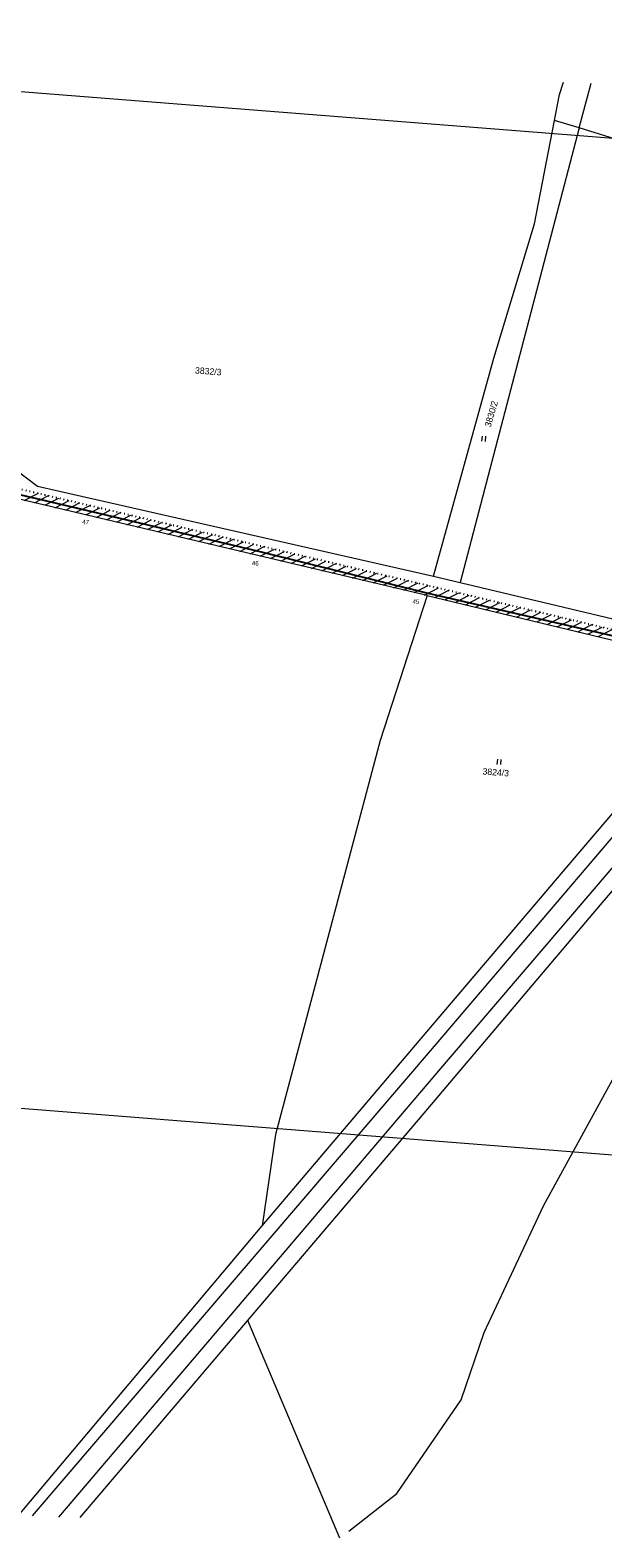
# Model space of a CAD drawing. Extents: x -686682 to -685519, y -959675 to -959188.
# Drawn here: x -686425.7 to -686257.7, y -959630.4 to -959188.4 of the extents above; entities that cross this region are included whole.
import ezdxf

# ---------------------------------------------------------------- set-up
doc = ezdxf.new("R2010")
doc.units = 0
doc.header["$LTSCALE"] = 0.76
doc.linetypes.add('DOTTED', pattern=[1.5, 0.3, -1.2])
for name, color, linetype, lineweight in [('1', 7, 'Continuous', 13), ('2', 7, 'Continuous', 25), ('3', 7, 'Continuous', 13)]:
    doc.layers.add(name, color=color, linetype=linetype, lineweight=lineweight)

msp = doc.modelspace()

# ---------------------------------------------------------------- linework, layer by layer
at = {"layer": '1'}
for p, q in [((-686270.4, -959207.3), (-686269.309, -959203.717)), ((-686264.72, -959217.11), (-686261.186, -959204.032)), ((-686264.72, -959217.11), (-686299.547, -959350.353)), ((-686264.72, -959217.11), (-686271.87, -959214.9)), ((-686159.97, -959249.46), (-686264.72, -959217.11)), ((-686293.16, -959307.411), (-686293.277, -959308.907)), ((-686292.163, -959307.49), (-686292.28, -959308.985)), ((-686288.662, -959402.161), (-686288.779, -959403.657)), ((-686287.665, -959402.24), (-686287.782, -959403.735)), ((-686307.203, -959486.217), (-686425.131, -959623.929)), ((-686417.348, -959624.293), (-686302.965, -959490.206)), ((-686362.008, -959566.628), (-686334.948, -959630.387))]:
    msp.add_line(p, q, dxfattribs=at)
for points in [[(-686681.662, -959484.53), (-685585.053, -959570.835), (-685561.751, -959274.75), (-686658.36, -959188.445)], [(-686407.67, -959329.7), (-686407.67, -959329.5), (-686407.47, -959329.5), (-686407.47, -959329.7)], [(-686357.95, -959341.59), (-686357.95, -959341.39), (-686357.75, -959341.39), (-686357.75, -959341.59)], [(-686309.41, -959353.59), (-686309.41, -959353.39), (-686309.21, -959353.39), (-686309.21, -959353.59)]]:
    msp.add_lwpolyline(points, close=True, dxfattribs=at)
for points in [[(-686307.4, -959348.5), (-686289.7, -959284.6), (-686277.74, -959245.2), (-686271.87, -959214.9), (-686270.4, -959207.3)], [(-686309.3, -959354.2), (-686524.18, -959303.43), (-686541.702, -959398.796)], [(-686458.24, -959312.86), (-686451.732, -959314.227), (-686446.754, -959312.429), (-686430.025, -959317.268), (-686423.527, -959322.107), (-686307.4, -959348.5), (-686224.763, -959368.147), (-686220.097, -959362.081), (-686213.119, -959368.991)], [(-686309.3, -959354.2), (-686323.08, -959396.66), (-686353.78, -959512.2), (-686357.67, -959538.9)], [(-686309.3, -959354.2), (-686227.11, -959373.87), (-686223.26, -959380.92)], [(-686431.3, -959626.4), (-686394.6, -959582.79), (-686357.67, -959538.9), (-686311.01, -959484.06), (-686264.36, -959429.23), (-686223.26, -959380.92)], [(-686258.52, -959444.88), (-686310.23, -959505.92), (-686411.165, -959624.439)], [(-686332.261, -959628.476), (-686318.169, -959617.351), (-686299.256, -959589.908), (-686292.581, -959570.161), (-686275.151, -959533.076), (-686249.847, -959486.812)]]:
    msp.add_lwpolyline(points, dxfattribs=at)
at = {"layer": '1', "linetype": 'DOTTED', "lineweight": 25}
msp.add_lwpolyline([(-686525.77, -959299.98), (-686308.601, -959351.282), (-686225.3, -959371.218)], dxfattribs=at)
at = {"layer": '2', "lineweight": 13}
for p, q in [((-686148.779, -959300.309), (-686307.203, -959486.217)), ((-686302.965, -959490.206), (-686211.461, -959383.153)), ((-686208.563, -959385.893), (-686258.52, -959444.88))]:
    msp.add_line(p, q, dxfattribs=at)
at = {"layer": '2'}
msp.add_lwpolyline([(-686225.48, -959373.57), (-686228.71, -959372.1), (-686243.11, -959368.73), (-686309.31, -959353.49), (-686357.85, -959341.49), (-686407.57, -959329.6), (-686461.35, -959317.07), (-686504.66, -959307.42)], dxfattribs=at)
at = {"layer": '3'}
for p, q in [((-686427.431, -959326.288), (-686423.304, -959324.185)), ((-686424.421, -959327), (-686420.294, -959324.896)), ((-686421.412, -959327.711), (-686417.284, -959325.607)), ((-686418.402, -959328.422), (-686414.274, -959326.318)), ((-686415.392, -959329.133), (-686411.264, -959327.03)), ((-686412.382, -959329.844), (-686408.254, -959327.741)), ((-686409.373, -959330.555), (-686405.244, -959328.452)), ((-686406.363, -959331.266), (-686402.234, -959329.163)), ((-686403.353, -959331.977), (-686399.224, -959329.874)), ((-686400.343, -959332.688), (-686396.215, -959330.585)), ((-686397.334, -959333.4), (-686393.205, -959331.296)), ((-686394.324, -959334.111), (-686390.195, -959332.007)), ((-686391.314, -959334.822), (-686387.185, -959332.718)), ((-686388.304, -959335.533), (-686384.175, -959333.429)), ((-686385.295, -959336.244), (-686381.165, -959334.14)), ((-686382.285, -959336.955), (-686378.155, -959334.851)), ((-686379.275, -959337.666), (-686375.145, -959335.562)), ((-686376.265, -959338.377), (-686372.135, -959336.273)), ((-686373.256, -959339.088), (-686369.126, -959336.984)), ((-686370.246, -959339.8), (-686366.116, -959337.695)), ((-686367.236, -959340.511), (-686363.106, -959338.406)), ((-686364.227, -959341.222), (-686360.096, -959339.117)), ((-686361.217, -959341.933), (-686357.086, -959339.828)), ((-686358.207, -959342.644), (-686354.076, -959340.539)), ((-686355.197, -959343.355), (-686351.066, -959341.25)), ((-686352.188, -959344.066), (-686348.056, -959341.961)), ((-686349.178, -959344.777), (-686345.046, -959342.672)), ((-686346.168, -959345.489), (-686342.037, -959343.383)), ((-686343.158, -959346.2), (-686339.027, -959344.094)), ((-686340.149, -959346.911), (-686336.017, -959344.805)), ((-686337.139, -959347.622), (-686333.007, -959345.516)), ((-686334.129, -959348.333), (-686329.997, -959346.228)), ((-686331.119, -959349.044), (-686326.987, -959346.939)), ((-686328.11, -959349.755), (-686323.977, -959347.65)), ((-686325.1, -959350.466), (-686320.967, -959348.361)), ((-686322.09, -959351.177), (-686317.957, -959349.072)), ((-686319.08, -959351.889), (-686314.947, -959349.783)), ((-686316.071, -959352.6), (-686311.938, -959350.494)), ((-686313.061, -959353.311), (-686308.928, -959351.205)), ((-686310.051, -959354.022), (-686305.929, -959351.921)), ((-686307.051, -959354.738), (-686302.931, -959352.639)), ((-686304.053, -959355.455), (-686299.934, -959353.356)), ((-686301.056, -959356.172), (-686296.936, -959354.074)), ((-686298.058, -959356.89), (-686293.939, -959354.791)), ((-686295.061, -959357.607), (-686290.942, -959355.508)), ((-686292.063, -959358.325), (-686287.944, -959356.226)), ((-686289.066, -959359.042), (-686284.947, -959356.943)), ((-686286.068, -959359.759), (-686281.949, -959357.66)), ((-686283.071, -959360.477), (-686278.952, -959358.378)), ((-686280.073, -959361.194), (-686275.954, -959359.095)), ((-686277.076, -959361.911), (-686272.957, -959359.812)), ((-686274.079, -959362.629), (-686269.959, -959360.53)), ((-686271.081, -959363.346), (-686266.962, -959361.247)), ((-686268.084, -959364.063), (-686263.964, -959361.965)), ((-686265.086, -959364.781), (-686260.967, -959362.682)), ((-686262.089, -959365.498), (-686257.969, -959363.399)), ((-686259.091, -959366.216), (-686254.972, -959364.117))]:
    msp.add_line(p, q, dxfattribs=at)

# ---------------------------------------------------------------- texts
at = {"layer": '1'}
for s, height, rotation, p in [('3832/3', 1.9, 355.5, (-686377.417, -959289.076)), ('3830/2', 1.9, 73.8, (-686290.64, -959304.946)), ('47', 1.3, 355.5, (-686410.5, -959333.206)), ('46', 1.3, 355.5, (-686360.705, -959345.264)), ('45', 1.3, 355.5, (-686313.603, -959356.528)), ('3824/3', 1.9, 355.5, (-686293.076, -959406.629))]:
    msp.add_text(s, height=height, rotation=rotation, dxfattribs=at).set_placement(p)

doc.saveas('drawing.dxf')
